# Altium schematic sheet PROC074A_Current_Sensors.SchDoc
size 431 x 279 mm; Date: Not shown in title block; ApprovedBy: Not shown in title block; CheckedBy: Not shown in title block; Author: Not shown in title block; CompanyName: Not shown in title block; Engineer: Not shown in title block; Organization: Not shown in title block; Address1: Not shown in title block; Address2: Not shown in title block; Address3: Not shown in title block; Address4: Not shown in title block; DocumentNumber: 1; Revision: Use project parameter SCH_Rev; SheetNumber: 6; SheetTotal: 22; PageSetup: Record=PageOptions¦CenterHorizontal=True¦CenterVertical=True¦PrintScale=1.00¦XCorrection=1.00¦YCorrection=1.00¦PrintKind=0¦BorderSize=5000000¦LeftOffset=0¦BottomOffset=0¦Orientation=2¦PaperLength=1000¦PaperWidth=1000¦Scale=100¦PaperSource=15¦PrintQuality=600¦MediaType=1¦DitherType=10¦PaperKind=Letter¦PrintScaleMode=1
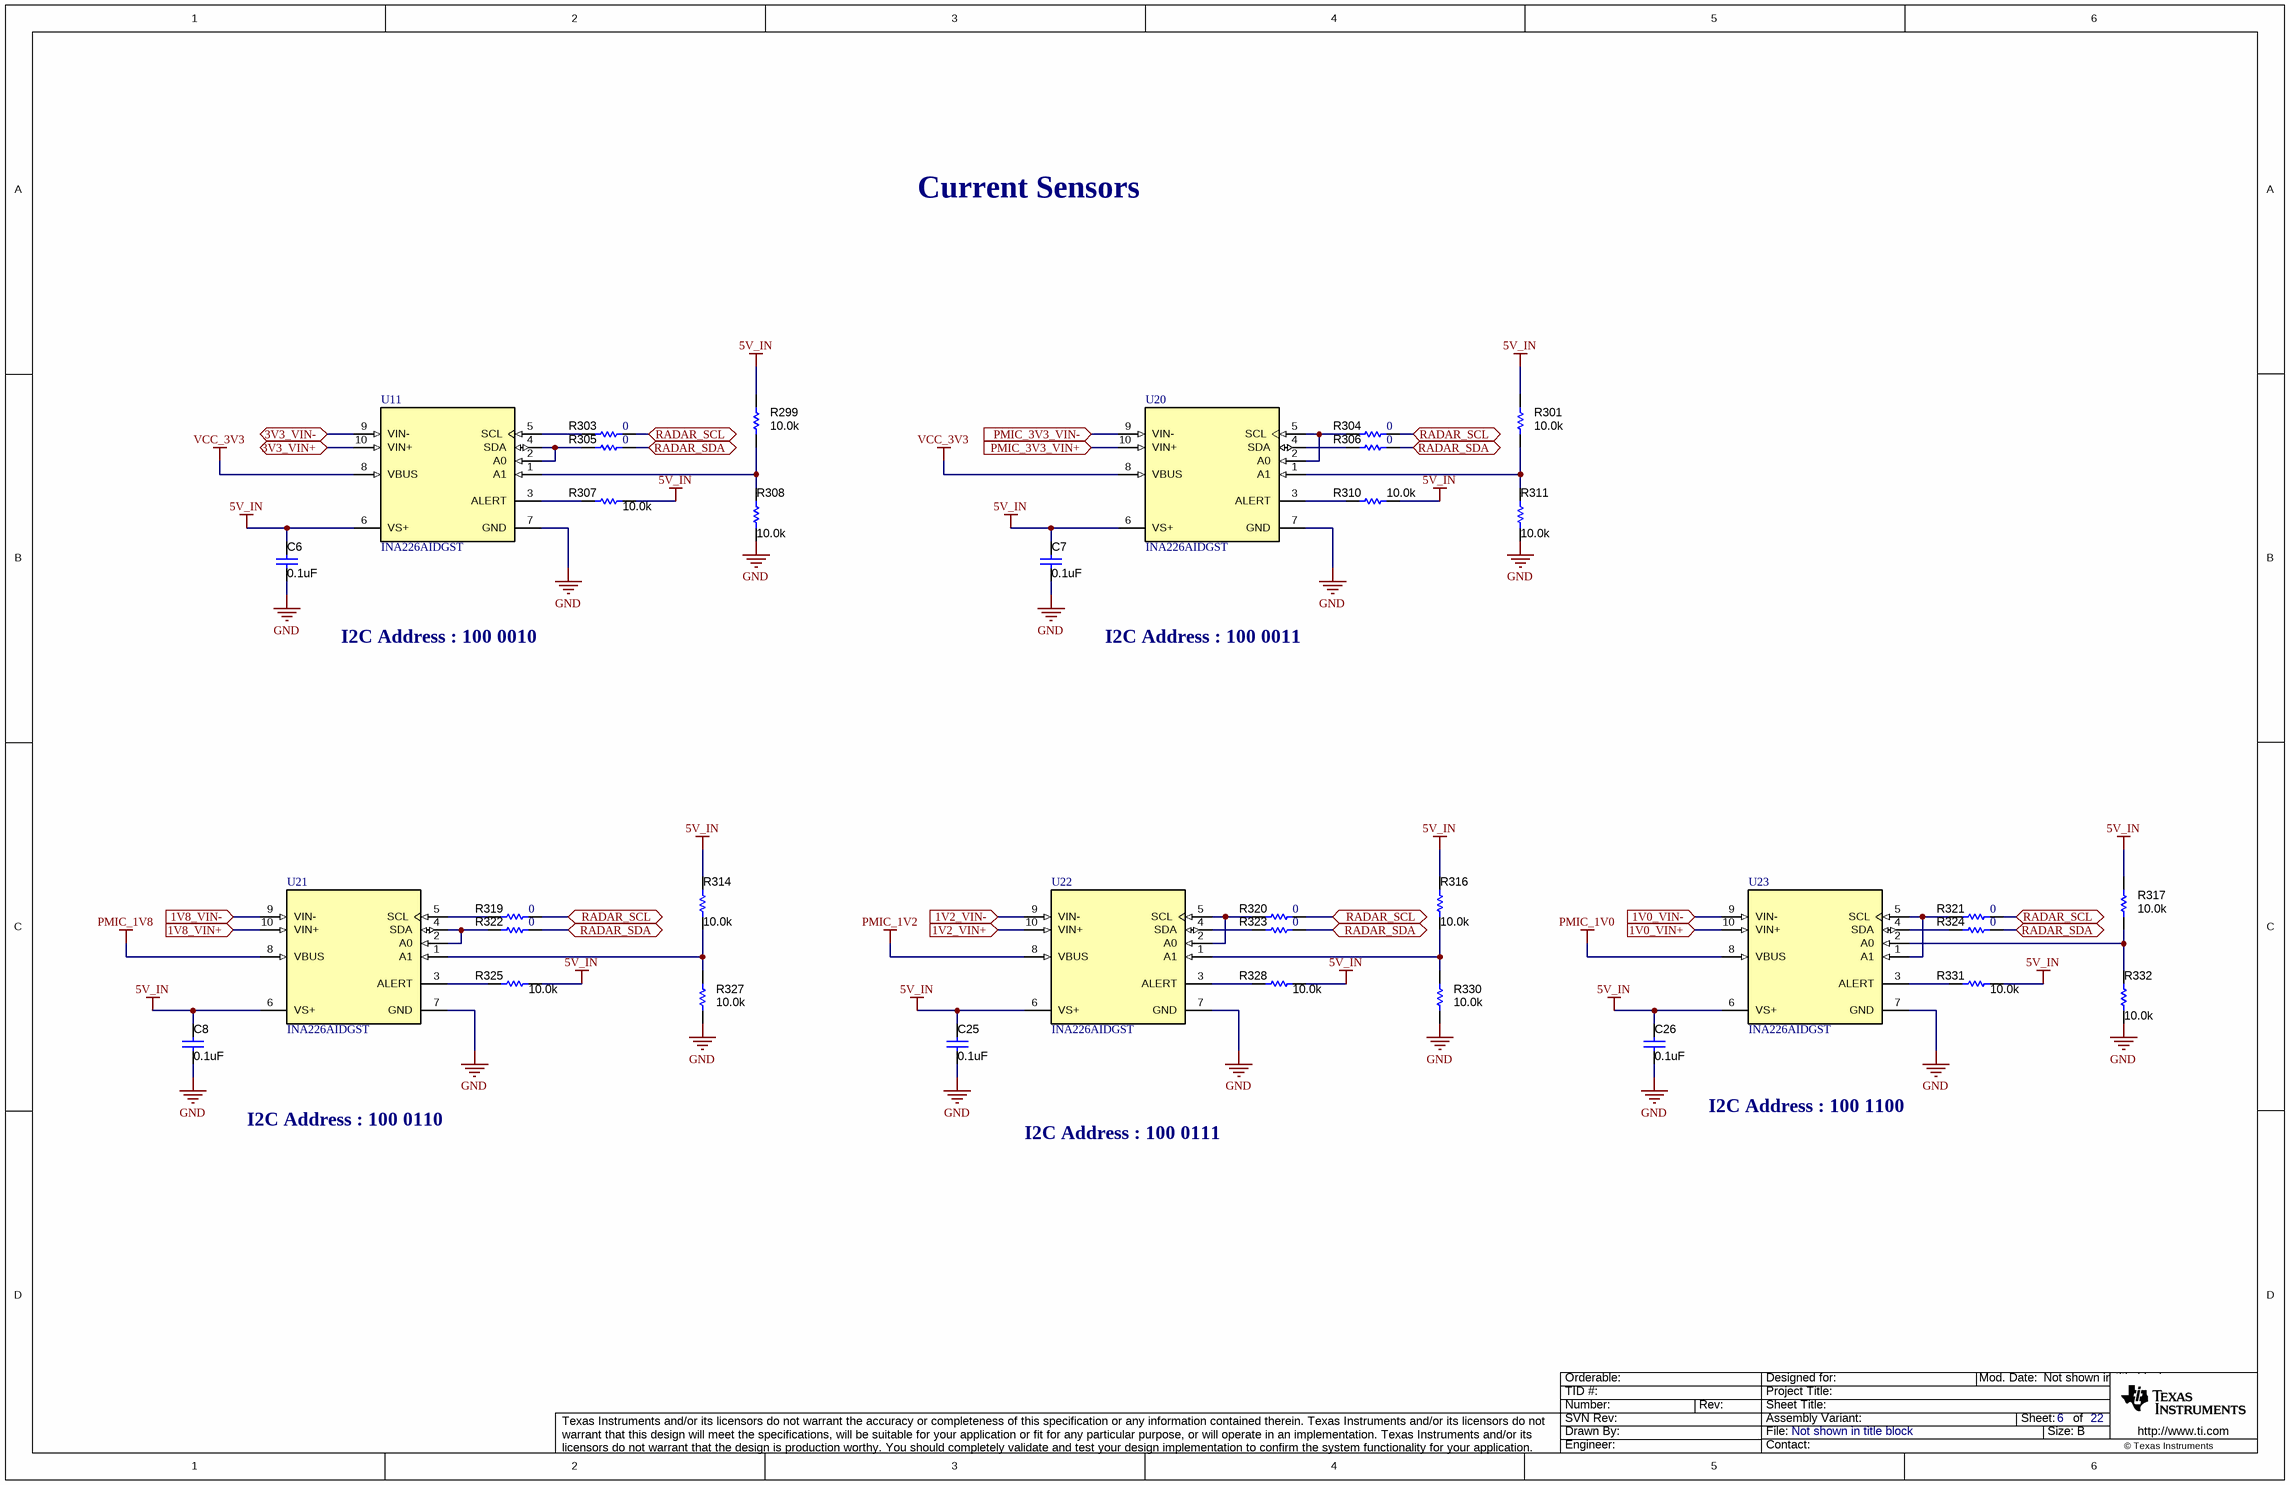
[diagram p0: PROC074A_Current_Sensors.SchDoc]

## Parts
C6  ValueDisplayed: 0.1uF  [0402L]  (hidden comment: CGA2B3X7R1H104K050BB)
C7  ValueDisplayed: 0.1uF  [0402L]  (hidden comment: CGA2B3X7R1H104K050BB)
C8  ValueDisplayed: 0.1uF  [0402L]  (hidden comment: CGA2B3X7R1H104K050BB)
C25  ValueDisplayed: 0.1uF  [0402L]  (hidden comment: CGA2B3X7R1H104K050BB)
C26  ValueDisplayed: 0.1uF  [0402L]  (hidden comment: CGA2B3X7R1H104K050BB)
R299  ValueDisplayed: 10.0k  [0402L]  (hidden comment: CRCW040210K0FKED)
R301  ValueDisplayed: 10.0k  [0402L]  (hidden comment: CRCW040210K0FKED)
R303  ValueDisplayed: 0  [0201]  (hidden comment: CRCW02010000Z0ED)
R304  ValueDisplayed: 0  [0201]  (hidden comment: CRCW02010000Z0ED)
R305  ValueDisplayed: 0  [0201]  (hidden comment: CRCW02010000Z0ED)
R306  ValueDisplayed: 0  [0201]  (hidden comment: CRCW02010000Z0ED)
R307  ValueDisplayed: 10.0k  [0402L]  (hidden comment: CRCW040210K0FKED)
R308  ValueDisplayed: 10.0k  [0402L]  (hidden comment: CRCW040210K0FKED)
R310  ValueDisplayed: 10.0k  [0402L]  (hidden comment: CRCW040210K0FKED)
R311  ValueDisplayed: 10.0k  [0402L]  (hidden comment: CRCW040210K0FKED)
R314  ValueDisplayed: 10.0k  [0402L]  (hidden comment: CRCW040210K0FKED)
R316  ValueDisplayed: 10.0k  [0402L]  (hidden comment: CRCW040210K0FKED)
R317  ValueDisplayed: 10.0k  [0402L]  (hidden comment: CRCW040210K0FKED)
R319  ValueDisplayed: 0  [0201]  (hidden comment: CRCW02010000Z0ED)
R320  ValueDisplayed: 0  [0201]  (hidden comment: CRCW02010000Z0ED)
R321  ValueDisplayed: 0  [0201]  (hidden comment: CRCW02010000Z0ED)
R322  ValueDisplayed: 0  [0201]  (hidden comment: CRCW02010000Z0ED)
R323  ValueDisplayed: 0  [0201]  (hidden comment: CRCW02010000Z0ED)
R324  ValueDisplayed: 0  [0201]  (hidden comment: CRCW02010000Z0ED)
R325  ValueDisplayed: 10.0k  [0402L]  (hidden comment: CRCW040210K0FKED)
R327  ValueDisplayed: 10.0k  [0402L]  (hidden comment: CRCW040210K0FKED)
R328  ValueDisplayed: 10.0k  [0402L]  (hidden comment: CRCW040210K0FKED)
R330  ValueDisplayed: 10.0k  [0402L]  (hidden comment: CRCW040210K0FKED)
R331  ValueDisplayed: 10.0k  [0402L]  (hidden comment: CRCW040210K0FKED)
R332  ValueDisplayed: 10.0k  [0402L]  (hidden comment: CRCW040210K0FKED)
U11  INA226AIDGST  [DGS0010A_L]
U20  INA226AIDGST  [DGS0010A_L]
U21  INA226AIDGST  [DGS0010A_L]
U22  INA226AIDGST  [DGS0010A_L]
U23  INA226AIDGST  [DGS0010A_L]

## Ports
1V0_VIN+ (in), 1V0_VIN- (in), 1V2_VIN+ (in), 1V2_VIN- (in), 1V8_VIN+ (in), 1V8_VIN- (in), 3V3_VIN+, 3V3_VIN-, PMIC_3V3_VIN+ (in), PMIC_3V3_VIN- (in), RADAR_SCL, RADAR_SDA

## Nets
5V_IN: C6.2 C7.2 C8.2 C25.2 C26.2 R299.2 R301.2 R307.1 R310.1 R314.2 R316.2 R317.2 R325.1 R328.1 R331.1 U11.6(VS+) U20.6(VS+) U21.6(VS+) U22.6(VS+) U23.6(VS+)
GND: C6.1 C7.1 C8.1 C25.1 C26.1 R308.1 R311.1 R327.1 R330.1 R332.1 U11.7(GND) U20.7(GND) U21.7(GND) U22.7(GND) U23.7(GND)
PMIC_1V0: U23.8(VBUS)
PMIC_1V2: U22.8(VBUS)
PMIC_1V8: U21.8(VBUS)
VCC_3V3: U11.8(VBUS) U20.8(VBUS)
1V0_VIN+: U23.10(VIN+) ; port 1V0_VIN+
1V0_VIN-: U23.9(VIN-) ; port 1V0_VIN-
1V2_VIN+: U22.10(VIN+) ; port 1V2_VIN+
1V2_VIN-: U22.9(VIN-) ; port 1V2_VIN-
1V8_VIN+: U21.10(VIN+) ; port 1V8_VIN+
1V8_VIN-: U21.9(VIN-) ; port 1V8_VIN-
3V3_VIN+: U11.10(VIN+) ; port 3V3_VIN+
3V3_VIN-: U11.9(VIN-) ; port 3V3_VIN-
PMIC_3V3_VIN+: U20.10(VIN+) ; port PMIC_3V3_VIN+
PMIC_3V3_VIN-: U20.9(VIN-) ; port PMIC_3V3_VIN-
RADAR_SCL: R303.2 R304.2 R319.2 R320.2 R321.2 ; port RADAR_SCL
RADAR_SDA: R305.2 R306.2 R322.2 R323.2 R324.2 ; port RADAR_SDA
NetR299_1: R299.1 R308.2 U11.1(A1)
NetR301_1: R301.1 R311.2 U20.1(A1)
NetR303_1: R303.1 U11.5(SCL)
NetR304_1: R304.1 U20.2(A0) U20.5(SCL)
NetR305_1: R305.1 U11.2(A0) U11.4(SDA)
NetR306_1: R306.1 U20.4(SDA)
NetR307_2: R307.2 U11.3(ALERT)
NetR310_2: R310.2 U20.3(ALERT)
NetR314_1: R314.1 R327.2 U21.1(A1)
NetR316_1: R316.1 R330.2 U22.1(A1)
NetR317_1: R317.1 R332.2 U23.2(A0)
NetR319_1: R319.1 U21.5(SCL)
NetR320_1: R320.1 U22.2(A0) U22.5(SCL)
NetR321_1: R321.1 U23.1(A1) U23.5(SCL)
NetR322_1: R322.1 U21.2(A0) U21.4(SDA)
NetR323_1: R323.1 U22.4(SDA)
NetR324_1: R324.1 U23.4(SDA)
NetR325_2: R325.2 U21.3(ALERT)
NetR328_2: R328.2 U22.3(ALERT)
NetR331_2: R331.2 U23.3(ALERT)

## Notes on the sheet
- Current Sensors
- I2C Address : 100 0010
- I2C Address : 100 0011
- I2C Address : 100 0110
- I2C Address : 100 0111
- I2C Address : 100 1100

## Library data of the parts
C6-C8 C25 C26 = CMP-0006325-2: CAP, CERM, 0.1 uF, 50 V, +/- 10%, X7R, AEC-Q200 Grade 1, 0402; Manufacturer: TDK; TaMin_C: -55°C; ESR_ohm: 0.039064; Polarized: N; SizeAreaWB_mm2: 3; Value1: 0.039064 ohm; U/M: EA; Value: 0.1uF; TaMax_C: 125°C; SizeZ_mm: 0.6; SizeX_mm: 1; SizeY_mm: 0.5; Cap_Case: 0402; Value2: 50V; CompType: Capacitor; AEC Qualified: Y; Cap_F: 100nF; IRMS_A: 8.14669dA; AEC Category: Q200
R299 R301 R317 R327 R330 = CMP-0025958-2: RES, 10.0 k, 1%, 0.063 W, 0402; Manufacturer: Vishay-Dale; Power_W: 63mW; TempCo: 100 ppm/C; Value_Code: 10k0; U/M: EA; Value: 10.0k; EIA_Code: E96; Res_ohm: 10k; SizeX_mm: 1; SizeY_mm: 0.5; SizeZ_mm: 0.6; Value2: 0.063W; CompType: Resistor; VDC_V: 50V; AEC Category: Q200; INSTALLATION: DNP
R303 = CMP-0027008-4: RES, 0, 5%, 0.05 W, 0201; Manufacturer: Vishay-Dale; Power_W: 50mW; TempCo: ppm/C; Value_Code: 0000; Value: 0; EIA_Code: E24; SizeX_mm: 0.6; SizeY_mm: 0.3; SizeZ_mm: 0.26; Value2: 0.05W; SizeArea_mm2: 0.18; CompType: Resistor; AEC Qualified: N; AEC Category: Q200; INSTALLATION: DNP
R304-R306 R319-R324 = CMP-0027008-4: RES, 0, 5%, 0.05 W, 0201; Manufacturer: Vishay-Dale; Power_W: 50mW; TempCo: ppm/C; Value_Code: 0000; Value: 0; EIA_Code: E24; SizeX_mm: 0.6; SizeY_mm: 0.3; SizeZ_mm: 0.26; Value2: 0.05W; SizeArea_mm2: 0.18; AEC Qualified: N; AEC Category: Q200
R307 R308 R310 R311 R314 R316 R325 R328 R331 R332 = CMP-0025958-2: RES, 10.0 k, 1%, 0.063 W, 0402; Manufacturer: Vishay-Dale; Power_W: 63mW; TempCo: 100 ppm/C; Value_Code: 10k0; U/M: EA; Value: 10.0k; EIA_Code: E96; Res_ohm: 10k; SizeX_mm: 1; SizeY_mm: 0.5; SizeZ_mm: 0.6; Value2: 0.063W; VDC_V: 50V; AEC Category: Q200
U11 U20-U23 = CMP-0037978-1: High-Side Measurement, Bi-Directional Current / Power Monitor with I2C Interface, 2.7 to 5.5 V, -40 to 125 degC, 10-pin SOP (DGS10), Green (RoHS & no Sb/Br); Vs(Min)(V): 2.7; Rating: Catalog; Quiescent Current (+/-)(Typ)(mA): 0.33; Input Offset (+/-)(Max)(uV): 10; CMRR(Min)(dB): 126; Vs(Max)(V): 5.5; Common Mode Range(Max)(V): 36; Input Offset Drift (+/-)(Max)(uV/Degrees Celsius): 0.1; Common Mode Range(Min)(V): 0; SubFamily: Current Shunt Monitor; Gain(V/V): 1; Small-Signal Bandwidth(Typ)(MHz): 0.007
